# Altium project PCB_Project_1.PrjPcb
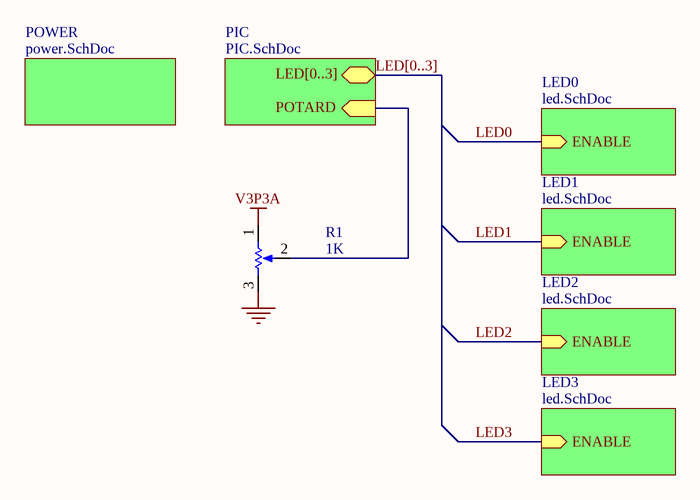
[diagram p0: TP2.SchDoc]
4 sheets, 34 parts. Net scope: hierarchical (ports join the sheet entries above them; power ports are global).
Sheets:
  TP2.SchDoc
    POWER = power.SchDoc
    PIC = PIC.SchDoc
    LED3 = led.SchDoc
    LED2 = led.SchDoc
    LED1 = led.SchDoc
    LED0 = led.SchDoc

## Sheet TP2.SchDoc
size A

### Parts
R1  1K  [PDB181-K415K-102A2]

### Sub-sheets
LED0 = led.SchDoc: ENABLE (in)
LED1 = led.SchDoc: ENABLE (in)
LED2 = led.SchDoc: ENABLE (in)
LED3 = led.SchDoc: ENABLE (in)
PIC = PIC.SchDoc: no entries
POWER = power.SchDoc: no entries

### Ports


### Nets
GND: R1.3(TOP)
V3P3A: R1.1(BOT)
NetR1_2: R1.2(TAP) ; port 

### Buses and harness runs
bus LED[0..3]
bus LED[0..3] = port 

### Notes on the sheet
- Labels drawn without touching a wire or pin: LED[0..3], POTARD

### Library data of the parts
R1 = RPot: Potentiometer; Sim Note: Enter the Resistance value and the set point into parameter fields.; Set Position: 0.5; Fabricant: BOURNS; Fournisseur: Farnell; RefFournisseur: 1823540

## Sheet power.SchDoc
size A
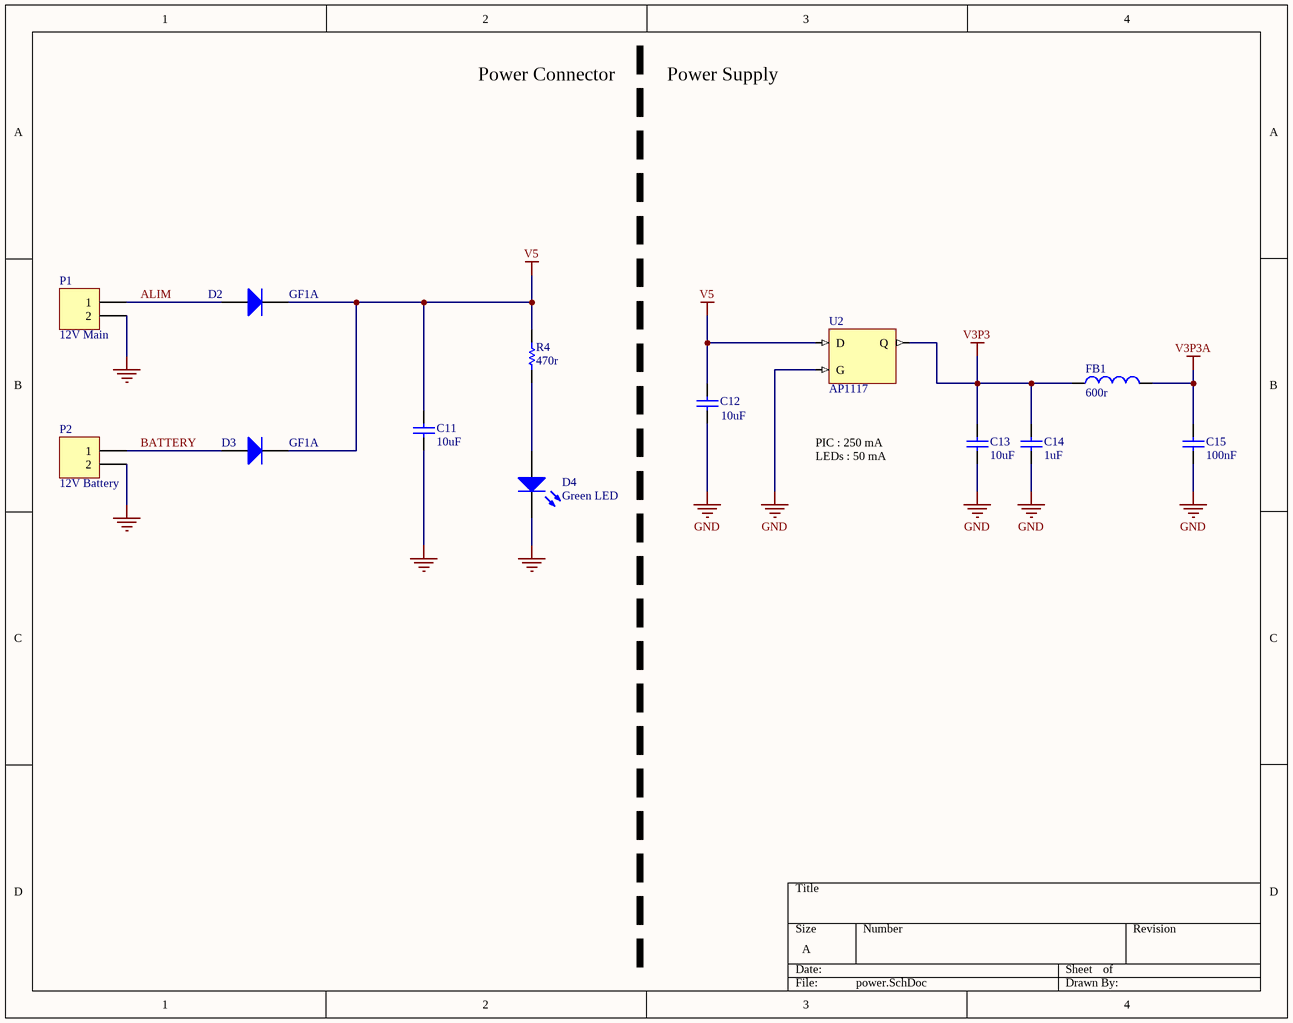
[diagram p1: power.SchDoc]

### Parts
C11  10uF  [CAPC2012N]
C12  10uF  [CAPC2012N]
C13  10uF  [CAPC2012N]
C14  1uF  [CAPC1608N]
C15  100nF  [RAD-0.3]
D2  GF1A  [SMA/DO-214AC_21]
D3  GF1A  [SMA/DO-214AC_21]
D4  Green LED  [LED 0805]
FB1  600r  [INDC1608AN]
P1  12V Main  [PHOENIX_1985195]
P2  12V Battery  [PHOENIX_1985195]
R4  470r  [RESC1608N]
U2  AP1117  [TD03B_N]

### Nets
GND: C11.1 C12.1 C13.1 C14.1 C15.1 D4.2(K) P1.2 P2.2 U2.G
V3P3: C13.2 C14.2 FB1.1 U2.Q
V3P3A: C15.2 FB1.2
V5: C11.2 C12.2 D2.2(K) D3.2(K) R4.2 U2.D
ALIM: D2.1(A) P1.1
BATTERY: D3.1(A) P2.1
NetD4_1: D4.1(A) R4.1

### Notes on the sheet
- Power Connector
- Power Supply
- PIC : 250 mA
- LEDs : 50 mA

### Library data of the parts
C11-C13 = Cap: Capacitor; Fabricant: TDK; RefFabricant: C2012X5R0J106M/1.25; Fournisseur: Farnell; RefFournisseur: 2309029; Precision: 6,3V X5R
C14 = Cap: Capacitor; Precision: 6,3V X5R
C15 = Cap: Capacitor; Value: 100pF
D2 D3 = Diode: Default Diode; Fabricant: VISHAY; RefFabricant: GF1A-E3/67A; Fournisseur: Farnell; RefFournisseur: 9549560
D4 = LED2: Typical RED, GREEN, YELLOW, AMBER GaAs LED; Fabricant: KINGBRIGHT; RefFabricant: KPT-2012SGC; Fournisseur: Farnell; RefFournisseur: 2099239
FB1 = Inductor: Code_IEC: 1005; Value: 10mH; Fabricant: Wurth; RefFabricant: 742792651; Fournisseur: Farnell; RefFournisseur: 1635706
P1 P2 = Header 2: Header, 2-Pin; Fabricant: PHOENIX CONTACT; RefFabricant: PTSA 1.5/2-3,5-Z; Fournisseur: Farnell; RefFournisseur: 1792769
R4 = Res1: Resistor; Value: 1K; Precision: 1%
U2 = LD: 1A LDO, 18V input, DPAK; FunctionalClass: Latch; ArchiveName: GENERIC; VHDLIB_SIM: GENERIC_LIB; Fabricant: DIODES INC; RefFabricant: AP1117D33G-13; Fournisseur: Farnell; RefFournisseur: 1825285

## Sheet PIC.SchDoc
size A
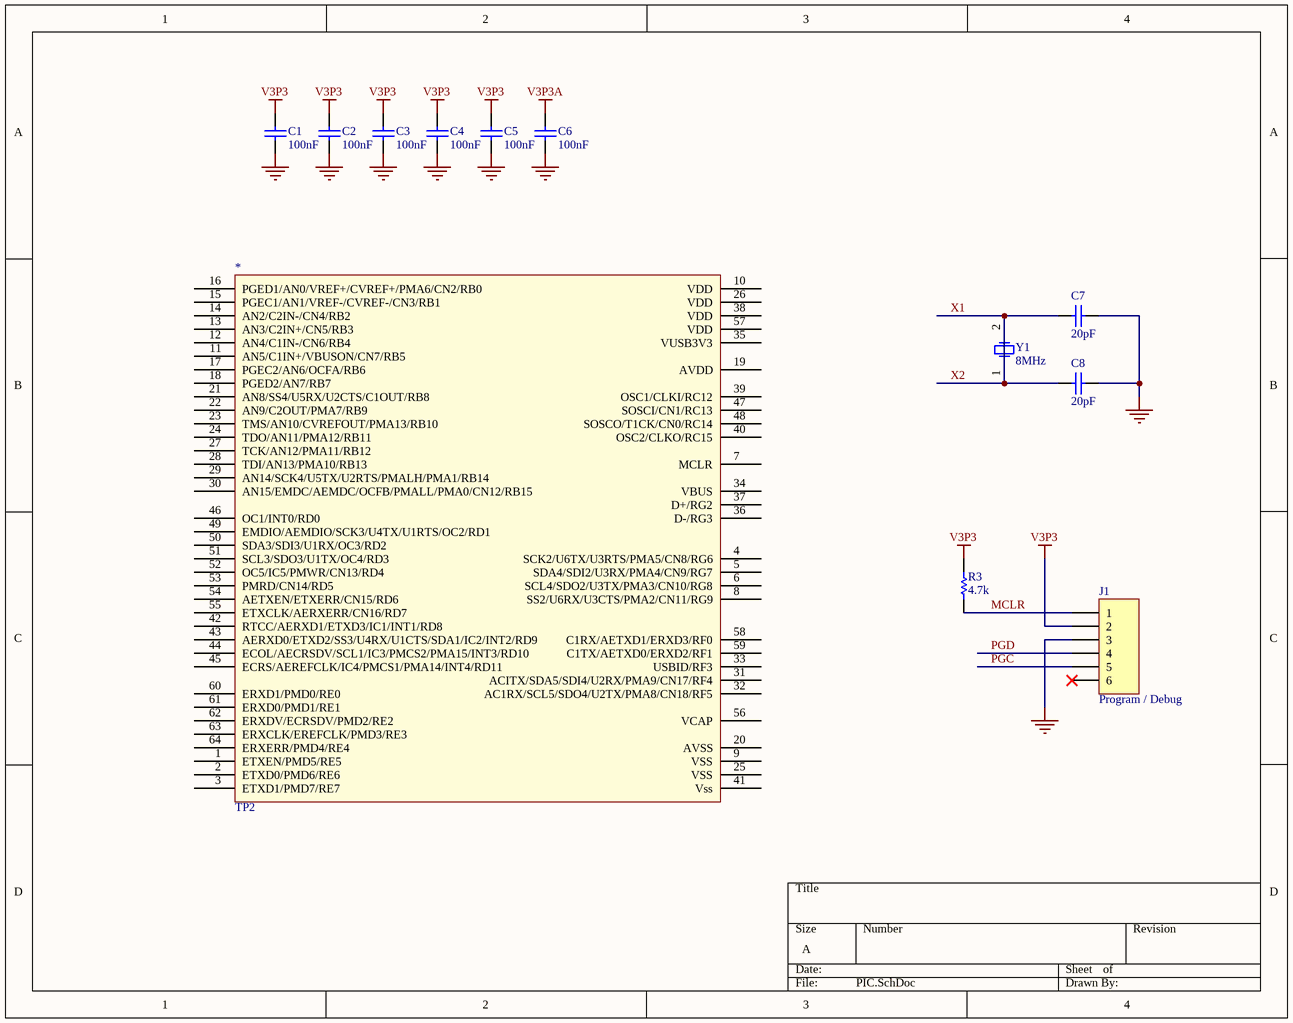
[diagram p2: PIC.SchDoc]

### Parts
*  TP2
C1  100nF  [CAPC1608N]
C2  100nF  [CAPC1608N]
C3  100nF  [CAPC1608N]
C4  100nF  [CAPC1608N]
C5  100nF  [CAPC1608N]
C6  100nF  [CAPC1608N]
C7  20pF  [CAPC1005N]
C8  20pF  [CAPC1005N]
J1  Program / Debug  [MOLEX 6P 1.25 CMS]
R3  4.7k  [RESC1608N]
Y1  8MHz  [XTAL139X50X45]

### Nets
GND: C1.1 C2.1 C3.1 C4.1 C5.1 C6.1 C7.2 C8.2 J1.3
V3P3: C1.2 C2.2 C3.2 C4.2 C5.2 J1.2 R3.2
V3P3A: C6.2
MCLR: J1.1 R3.1
PGC: J1.5
PGD: J1.4
X1: C7.1 C8.1 Y1.1(OSC1) Y1.2(OSC2)  [also labelled X2]

Not connected (* = marked no-connect by the designer): * 1(ETXEN/PMD5/RE5) 2(ETXD0/PMD6/RE6) 3(ETXD1/PMD7/RE7) 4(SCK2/U6TX/U3RTS/PMA5/CN8/RG6) 5(SDA4/SDI2/U3RX/PMA4/CN9/RG7) 6(SCL4/SDO2/U3TX/PMA3/CN10/RG8) 7(MCLR) 8(SS2/U6RX/U3CTS/PMA2/CN11/RG9) 9(VSS) 10(VDD) 11(AN5/C1IN+/VBUSON/CN7/RB5) 12(AN4/C1IN-/CN6/RB4) 13(AN3/C2IN+/CN5/RB3) 14(AN2/C2IN-/CN4/RB2) 15(PGEC1/AN1/VREF-/CVREF-/CN3/RB1) 16(PGED1/AN0/VREF+/CVREF+/PMA6/CN2/RB0) 17(PGEC2/AN6/OCFA/RB6) 18(PGED2/AN7/RB7) 19(AVDD) 20(AVSS) 21(AN8/SS4/U5RX/U2CTS/C1OUT/RB8) 22(AN9/C2OUT/PMA7/RB9) 23(TMS/AN10/CVREFOUT/PMA13/RB10) 24(TDO/AN11/PMA12/RB11) 25(VSS) 26(VDD) 27(TCK/AN12/PMA11/RB12) 28(TDI/AN13/PMA10/RB13) 29(AN14/SCK4/U5TX/U2RTS/PMALH/PMA1/RB14) 30(AN15/EMDC/AEMDC/OCFB/PMALL/PMA0/CN12/RB15) 31(ACITX/SDA5/SDI4/U2RX/PMA9/CN17/RF4) 32(AC1RX/SCL5/SDO4/U2TX/PMA8/CN18/RF5) 33(USBID/RF3) 34(VBUS) 35(VUSB3V3) 36(D-/RG3) 37(D+/RG2) 38(VDD) 39(OSC1/CLKI/RC12) 40(OSC2/CLKO/RC15) 41(Vss) 42(RTCC/AERXD1/ETXD3/IC1/INT1/RD8) 43(AERXD0/ETXD2/SS3/U4RX/U1CTS/SDA1/IC2/INT2/RD9) 44(ECOL/AECRSDV/SCL1/IC3/PMCS2/PMA15/INT3/RD10) 45(ECRS/AEREFCLK/IC4/PMCS1/PMA14/INT4/RD11) 46(OC1/INT0/RD0) 47(SOSCI/CN1/RC13) 48(SOSCO/T1CK/CN0/RC14) 49(EMDIO/AEMDIO/SCK3/U4TX/U1RTS/OC2/RD1) 50(SDA3/SDI3/U1RX/OC3/RD2) 51(SCL3/SDO3/U1TX/OC4/RD3) 52(OC5/IC5/PMWR/CN13/RD4) 53(PMRD/CN14/RD5) 54(AETXEN/ETXERR/CN15/RD6) 55(ETXCLK/AERXERR/CN16/RD7) 56(VCAP) 57(VDD) 58(C1RX/AETXD1/ERXD3/RF0) 59(C1TX/AETXD0/ERXD2/RF1) 60(ERXD1/PMD0/RE0) 61(ERXD0/PMD1/RE1) 62(ERXDV/ECRSDV/PMD2/RE2) 63(ERXCLK/EREFCLK/PMD3/RE3) 64(ERXERR/PMD4/RE4); J1 6*

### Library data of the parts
C1-C6 = Cap: Capacitor; Value: 100pF
C7 = Cap: Capacitor; Value: 100pF; Precision: 50V X5R
C8 = Cap: Capacitor; Precision: 50V X5R
J1 = Header 6H: Header, 6-Pin, Right Angle; Fabricant: Molex; RefFabricant: 53398-0671; Fournisseur: Farnell; RefFournisseur: 1125368
R3 = Res1: Resistor; Value: 1K; Precision: 1%
Y1 = XTAL: Crystal Oscillator; Fabricant: FOX ELECTRONICS; RefFabricant: FOXSDLF/080-20; Fournisseur: Farnell; RefFournisseur: 2063972

## Sheet led.SchDoc
size A
Used 4 times, as channels LED3, LED2, LED1, LED0. Parts and nets are listed once, with the designators drawn on the sheet.
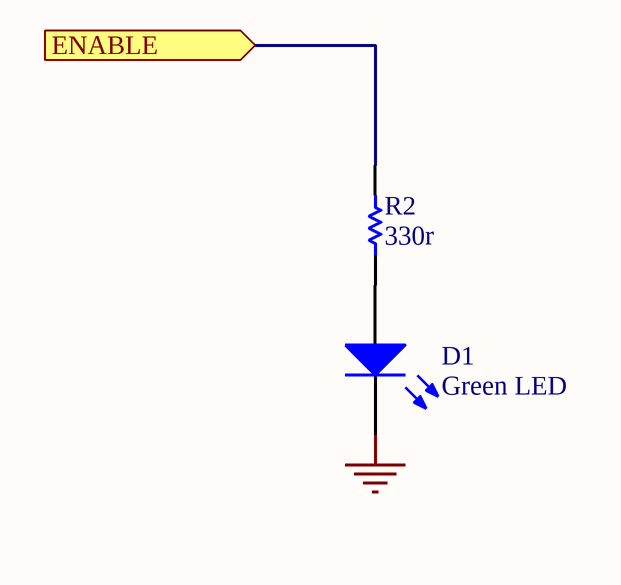
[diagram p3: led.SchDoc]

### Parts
D1  Green LED  [LED 0805]
R2  330r  [RESC1608N]

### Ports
ENABLE

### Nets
GND: D1.2(K)
ENABLE: R2.2 ; port ENABLE
NetD1_1: D1.1(A) R2.1

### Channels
LED3: designators end in _LED3; ports ENABLE=LED3
LED2: designators end in _LED2; ports ENABLE=LED2
LED1: designators end in _LED1; ports ENABLE=LED1
LED0: designators end in _LED0; ports ENABLE=LED0

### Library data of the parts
D1 = LED0: Typical INFRARED GaAs LED; Fabricant: KINGBRIGHT; RefFabricant: KPT-2012SGC; Fournisseur: Farnell; RefFournisseur: 2099239
R2 = Res1: Resistor; Value: 1K; Precision: 1%

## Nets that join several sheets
GND: TP2 (R1.3), power (9 pins), PIC (9 pins), LED3 (D1_LED3.2), LED2 (D1_LED2.2), LED1 (D1_LED1.2), LED0 (D1_LED0.2)
V3P3: power (C13.2 C14.2 FB1.1 U2.Q), PIC (7 pins)
V3P3A: TP2 (R1.1), power (C15.2 FB1.2), PIC (C6.2)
